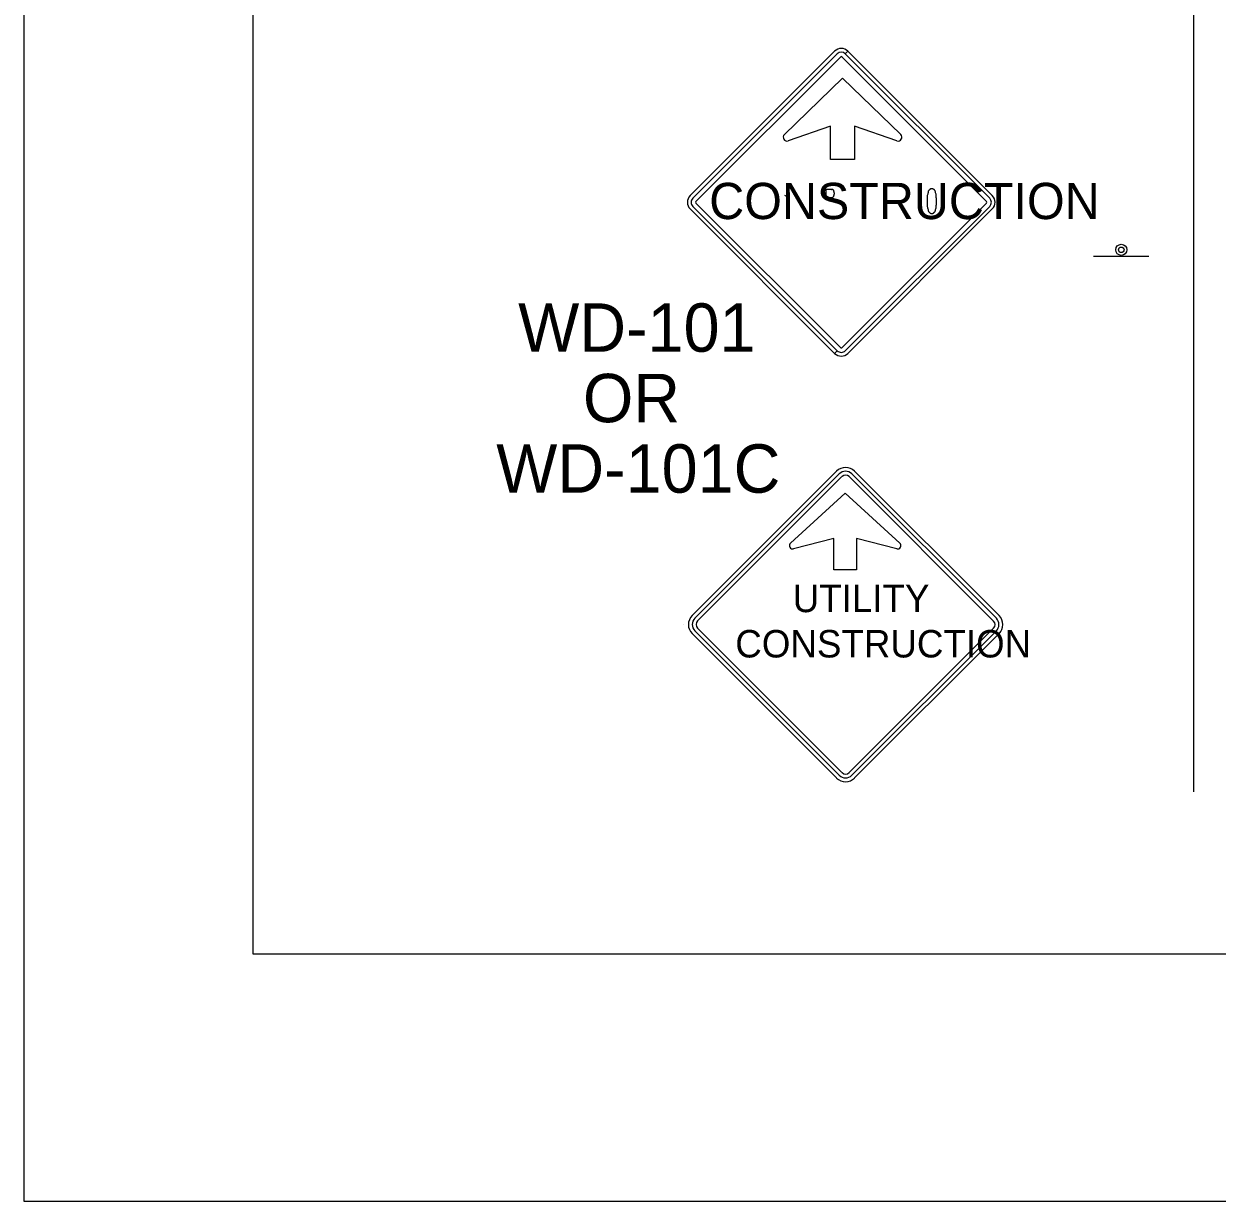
# Model space of a CAD drawing. Extents: x 1351 to 1567, y 178 to 457.
# Drawn here: x 1351.4 to 1403.6, y 177.9 to 229.4 of the extents above; entities that cross this region are included whole.
import ezdxf

# ---------------------------------------------------------------- set-up
doc = ezdxf.new("R2010")
doc.units = 0
for name, color, linetype in [('Level 1', 7, 'Continuous'), ('Level 10', 7, 'Continuous'), ('Level 44', 7, 'Continuous'), ('Level 60', 7, 'Continuous')]:
    doc.layers.add(name, color=color, linetype=linetype)

msp = doc.modelspace()

# ---------------------------------------------------------------- linework, layer by layer
at = {"layer": 'Level 1'}
for p, q in [((1380.523, 221.873), (1386.833, 228.183)), ((1380.523, 221.873), (1386.833, 228.183)), ((1380.638, 221.758), (1386.948, 228.068)), ((1380.638, 221.758), (1386.948, 228.068)), ((1380.776, 221.62), (1387.086, 227.93)), ((1380.776, 221.62), (1387.086, 227.93)), ((1387.164, 227.93), (1393.475, 221.62)), ((1387.164, 227.93), (1393.475, 221.62)), ((1387.417, 228.183), (1387.302, 228.068)), ((1387.417, 228.183), (1387.302, 228.068)), ((1387.302, 228.068), (1393.612, 221.758)), ((1387.302, 228.068), (1387.302, 228.068)), ((1387.302, 228.068), (1393.612, 221.758)), ((1387.302, 228.068), (1387.302, 228.068)), ((1387.417, 228.183), (1393.727, 221.873)), ((1387.417, 228.183), (1393.727, 221.873)), ((1384.64, 224.537), (1387.181, 227.012)), ((1384.64, 224.537), (1387.181, 227.012)), ((1387.182, 227.012), (1389.723, 224.537)), ((1387.182, 227.012), (1389.723, 224.537)), ((1386.655, 224.907), (1384.806, 224.268)), ((1386.655, 224.907), (1384.806, 224.268)), ((1386.655, 223.45), (1386.655, 224.907)), ((1386.655, 223.45), (1386.655, 224.907)), ((1389.557, 224.268), (1387.708, 224.907)), ((1387.708, 224.907), (1387.708, 223.45)), ((1389.557, 224.268), (1387.708, 224.907)), ((1387.708, 224.907), (1387.708, 223.45)), ((1387.708, 223.45), (1386.655, 223.45)), ((1387.708, 223.45), (1386.655, 223.45)), ((1386.684, 222.145), (1386.695, 222.145)), ((1386.684, 222.145), (1386.695, 222.145)), ((1386.684, 222.145), (1386.695, 222.145)), ((1386.684, 222.145), (1386.695, 222.145)), ((1386.833, 214.979), (1380.523, 221.289)), ((1386.833, 214.979), (1380.523, 221.289)), ((1386.948, 215.094), (1380.638, 221.404)), ((1386.948, 215.094), (1380.638, 221.404)), ((1387.086, 215.232), (1380.776, 221.542)), ((1387.086, 215.232), (1380.776, 221.542)), ((1393.475, 221.542), (1387.164, 215.232)), ((1393.475, 221.542), (1387.164, 215.232)), ((1393.612, 221.404), (1387.302, 215.094)), ((1393.612, 221.404), (1387.302, 215.094)), ((1393.727, 221.289), (1387.417, 214.979)), ((1393.727, 221.289), (1387.417, 214.979)), ((1386.948, 215.094), (1386.833, 214.979)), ((1386.948, 215.094), (1386.833, 214.979)), ((1386.833, 214.98), (1386.833, 214.979)), ((1386.833, 214.98), (1386.833, 214.979)), ((1386.948, 215.095), (1386.948, 215.094)), ((1386.948, 215.095), (1386.948, 215.094)), ((1387.101, 215.247), (1387.086, 215.232)), ((1387.101, 215.247), (1387.086, 215.232)), ((1385.04, 206.433), (1385.04, 206.433)), ((1385.04, 206.433), (1385.04, 206.433)), ((1385.04, 206.433), (1385.04, 206.433)), ((1385.04, 206.433), (1385.04, 206.433)), ((1385.04, 206.433), (1385.04, 206.433)), ((1385.04, 206.433), (1385.04, 206.433)), ((1380.216, 203.124), (1380.216, 203.124)), ((1380.216, 203.124), (1380.216, 203.124))]:
    msp.add_line(p, q, dxfattribs=at)
for points in [[(1386.695, 222.145), (1386.448, 222.145), (1386.448, 221.785), (1386.695, 221.785)], [(1386.695, 222.145), (1386.448, 222.145), (1386.448, 221.785), (1386.695, 221.785)], [(1386.695, 222.145), (1386.448, 222.145), (1386.448, 221.785), (1386.695, 221.785)], [(1386.695, 222.145), (1386.448, 222.145), (1386.448, 221.785), (1386.695, 221.785)], [(1386.684, 221.785), (1386.695, 221.785), (1386.707, 221.796), (1386.718, 221.796), (1386.729, 221.796), (1386.741, 221.796), (1386.741, 221.807), (1386.752, 221.807), (1386.763, 221.807), (1386.774, 221.819), (1386.786, 221.83), (1386.797, 221.841), (1386.808, 221.852), (1386.808, 221.864), (1386.808, 221.875), (1386.819, 221.897), (1386.819, 221.909), (1386.819, 221.92), (1386.819, 221.942), (1386.831, 221.954), (1386.831, 221.965), (1386.831, 221.987), (1386.819, 221.999), (1386.819, 222.01), (1386.819, 222.032), (1386.819, 222.044), (1386.808, 222.055), (1386.808, 222.078), (1386.797, 222.089), (1386.797, 222.1), (1386.786, 222.111), (1386.774, 222.111), (1386.774, 222.123), (1386.763, 222.123), (1386.752, 222.134), (1386.741, 222.134), (1386.729, 222.134), (1386.718, 222.145), (1386.707, 222.145), (1386.695, 222.145), (1386.684, 222.145)], [(1386.684, 221.785), (1386.695, 221.785), (1386.707, 221.796), (1386.718, 221.796), (1386.729, 221.796), (1386.741, 221.796), (1386.741, 221.807), (1386.752, 221.807), (1386.763, 221.807), (1386.774, 221.819), (1386.786, 221.83), (1386.797, 221.841), (1386.808, 221.852), (1386.808, 221.864), (1386.808, 221.875), (1386.819, 221.897), (1386.819, 221.909), (1386.819, 221.92), (1386.819, 221.942), (1386.831, 221.954), (1386.831, 221.965), (1386.831, 221.987), (1386.819, 221.999), (1386.819, 222.01), (1386.819, 222.032), (1386.819, 222.044), (1386.808, 222.055), (1386.808, 222.078), (1386.797, 222.089), (1386.797, 222.1), (1386.786, 222.111), (1386.774, 222.111), (1386.774, 222.123), (1386.763, 222.123), (1386.752, 222.134), (1386.741, 222.134), (1386.729, 222.134), (1386.718, 222.145), (1386.707, 222.145), (1386.695, 222.145), (1386.684, 222.145)], [(1386.684, 221.785), (1386.695, 221.785), (1386.707, 221.796), (1386.718, 221.796), (1386.729, 221.796), (1386.741, 221.796), (1386.741, 221.807), (1386.752, 221.807), (1386.763, 221.807), (1386.774, 221.819), (1386.786, 221.83), (1386.797, 221.841), (1386.808, 221.852), (1386.808, 221.864), (1386.808, 221.875), (1386.819, 221.897), (1386.819, 221.909), (1386.819, 221.92), (1386.819, 221.942), (1386.831, 221.954), (1386.831, 221.965), (1386.831, 221.987), (1386.819, 221.999), (1386.819, 222.01), (1386.819, 222.032), (1386.819, 222.044), (1386.808, 222.055), (1386.808, 222.078), (1386.797, 222.089), (1386.797, 222.1), (1386.786, 222.111), (1386.774, 222.111), (1386.774, 222.123), (1386.763, 222.123), (1386.752, 222.134), (1386.741, 222.134), (1386.729, 222.134), (1386.718, 222.145), (1386.707, 222.145), (1386.695, 222.145), (1386.684, 222.145)], [(1386.684, 221.785), (1386.695, 221.785), (1386.707, 221.796), (1386.718, 221.796), (1386.729, 221.796), (1386.741, 221.796), (1386.741, 221.807), (1386.752, 221.807), (1386.763, 221.807), (1386.774, 221.819), (1386.786, 221.83), (1386.797, 221.841), (1386.808, 221.852), (1386.808, 221.864), (1386.808, 221.875), (1386.819, 221.897), (1386.819, 221.909), (1386.819, 221.92), (1386.819, 221.942), (1386.831, 221.954), (1386.831, 221.965), (1386.831, 221.987), (1386.819, 221.999), (1386.819, 222.01), (1386.819, 222.032), (1386.819, 222.044), (1386.808, 222.055), (1386.808, 222.078), (1386.797, 222.089), (1386.797, 222.1), (1386.786, 222.111), (1386.774, 222.111), (1386.774, 222.123), (1386.763, 222.123), (1386.752, 222.134), (1386.741, 222.134), (1386.729, 222.134), (1386.718, 222.145), (1386.707, 222.145), (1386.695, 222.145), (1386.684, 222.145)], [(1390.93, 221.199), (1390.941, 221.188), (1390.941, 221.177), (1390.952, 221.165), (1390.964, 221.154), (1390.964, 221.143), (1390.975, 221.132), (1390.986, 221.132), (1390.997, 221.12), (1391.009, 221.12), (1391.009, 221.109), (1391.02, 221.109), (1391.031, 221.109), (1391.043, 221.098), (1391.054, 221.098), (1391.065, 221.098), (1391.076, 221.098), (1391.088, 221.098), (1391.099, 221.098), (1391.11, 221.098), (1391.121, 221.098), (1391.133, 221.109), (1391.144, 221.109), (1391.155, 221.109), (1391.166, 221.12), (1391.178, 221.132), (1391.189, 221.143), (1391.2, 221.143), (1391.2, 221.154), (1391.211, 221.165), (1391.223, 221.177), (1391.234, 221.188), (1391.234, 221.199), (1391.245, 221.233), (1391.245, 221.267), (1391.256, 221.301), (1391.268, 221.334), (1391.268, 221.368), (1391.279, 221.402), (1391.279, 221.447), (1391.29, 221.481), (1391.29, 221.515), (1391.29, 221.548), (1391.29, 221.582), (1391.29, 221.616), (1391.29, 221.65), (1391.29, 221.683), (1391.29, 221.717), (1391.29, 221.751), (1391.279, 221.796), (1391.279, 221.83), (1391.279, 221.864), (1391.268, 221.897), (1391.268, 221.931), (1391.256, 221.965), (1391.245, 221.999), (1391.245, 222.032), (1391.234, 222.066), (1391.223, 222.078), (1391.223, 222.089), (1391.211, 222.1), (1391.2, 222.111), (1391.2, 222.123), (1391.189, 222.134), (1391.178, 222.134), (1391.166, 222.145), (1391.155, 222.156), (1391.144, 222.156), (1391.133, 222.156), (1391.121, 222.168), (1391.11, 222.168), (1391.099, 222.168), (1391.088, 222.168), (1391.076, 222.168), (1391.065, 222.168), (1391.054, 222.168), (1391.043, 222.168), (1391.031, 222.168), (1391.02, 222.156), (1391.009, 222.156), (1391.009, 222.145), (1390.997, 222.145), (1390.986, 222.134), (1390.975, 222.134), (1390.975, 222.123), (1390.964, 222.111), (1390.952, 222.111), (1390.952, 222.1), (1390.941, 222.089), (1390.941, 222.078), (1390.93, 222.066), (1390.93, 222.055), (1390.93, 222.044), (1390.93, 222.032), (1390.919, 221.999), (1390.907, 221.976), (1390.907, 221.942), (1390.896, 221.909), (1390.885, 221.875), (1390.885, 221.841), (1390.885, 221.807)], [(1390.93, 221.199), (1390.941, 221.188), (1390.941, 221.177), (1390.952, 221.165), (1390.964, 221.154), (1390.964, 221.143), (1390.975, 221.132), (1390.986, 221.132), (1390.997, 221.12), (1391.009, 221.12), (1391.009, 221.109), (1391.02, 221.109), (1391.031, 221.109), (1391.043, 221.098), (1391.054, 221.098), (1391.065, 221.098), (1391.076, 221.098), (1391.088, 221.098), (1391.099, 221.098), (1391.11, 221.098), (1391.121, 221.098), (1391.133, 221.109), (1391.144, 221.109), (1391.155, 221.109), (1391.166, 221.12), (1391.178, 221.132), (1391.189, 221.143), (1391.2, 221.143), (1391.2, 221.154), (1391.211, 221.165), (1391.223, 221.177), (1391.234, 221.188), (1391.234, 221.199), (1391.245, 221.233), (1391.245, 221.267), (1391.256, 221.301), (1391.268, 221.334), (1391.268, 221.368), (1391.279, 221.402), (1391.279, 221.447), (1391.29, 221.481), (1391.29, 221.515), (1391.29, 221.548), (1391.29, 221.582), (1391.29, 221.616), (1391.29, 221.65), (1391.29, 221.683), (1391.29, 221.717), (1391.29, 221.751), (1391.279, 221.796), (1391.279, 221.83), (1391.279, 221.864), (1391.268, 221.897), (1391.268, 221.931), (1391.256, 221.965), (1391.245, 221.999), (1391.245, 222.032), (1391.234, 222.066), (1391.223, 222.078), (1391.223, 222.089), (1391.211, 222.1), (1391.2, 222.111), (1391.2, 222.123), (1391.189, 222.134), (1391.178, 222.134), (1391.166, 222.145), (1391.155, 222.156), (1391.144, 222.156), (1391.133, 222.156), (1391.121, 222.168), (1391.11, 222.168), (1391.099, 222.168), (1391.088, 222.168), (1391.076, 222.168), (1391.065, 222.168), (1391.054, 222.168), (1391.043, 222.168), (1391.031, 222.168), (1391.02, 222.156), (1391.009, 222.156), (1391.009, 222.145), (1390.997, 222.145), (1390.986, 222.134), (1390.975, 222.134), (1390.975, 222.123), (1390.964, 222.111), (1390.952, 222.111), (1390.952, 222.1), (1390.941, 222.089), (1390.941, 222.078), (1390.93, 222.066), (1390.93, 222.055), (1390.93, 222.044), (1390.93, 222.032), (1390.919, 221.999), (1390.907, 221.976), (1390.907, 221.942), (1390.896, 221.909), (1390.885, 221.875), (1390.885, 221.841), (1390.885, 221.807)], [(1390.93, 221.199), (1390.941, 221.188), (1390.941, 221.177), (1390.952, 221.165), (1390.964, 221.154), (1390.964, 221.143), (1390.975, 221.132), (1390.986, 221.132), (1390.997, 221.12), (1391.009, 221.12), (1391.009, 221.109), (1391.02, 221.109), (1391.031, 221.109), (1391.043, 221.098), (1391.054, 221.098), (1391.065, 221.098), (1391.076, 221.098), (1391.088, 221.098), (1391.099, 221.098), (1391.11, 221.098), (1391.121, 221.098), (1391.133, 221.109), (1391.144, 221.109), (1391.155, 221.109), (1391.166, 221.12), (1391.178, 221.132), (1391.189, 221.143), (1391.2, 221.143), (1391.2, 221.154), (1391.211, 221.165), (1391.223, 221.177), (1391.234, 221.188), (1391.234, 221.199), (1391.245, 221.233), (1391.245, 221.267), (1391.256, 221.301), (1391.268, 221.334), (1391.268, 221.368), (1391.279, 221.402), (1391.279, 221.447), (1391.29, 221.481), (1391.29, 221.515), (1391.29, 221.548), (1391.29, 221.582), (1391.29, 221.616), (1391.29, 221.65), (1391.29, 221.683), (1391.29, 221.717), (1391.29, 221.751), (1391.279, 221.796), (1391.279, 221.83), (1391.279, 221.864), (1391.268, 221.897), (1391.268, 221.931), (1391.256, 221.965), (1391.245, 221.999), (1391.245, 222.032), (1391.234, 222.066), (1391.223, 222.078), (1391.223, 222.089), (1391.211, 222.1), (1391.2, 222.111), (1391.2, 222.123), (1391.189, 222.134), (1391.178, 222.134), (1391.166, 222.145), (1391.155, 222.156), (1391.144, 222.156), (1391.133, 222.156), (1391.121, 222.168), (1391.11, 222.168), (1391.099, 222.168), (1391.088, 222.168), (1391.076, 222.168), (1391.065, 222.168), (1391.054, 222.168), (1391.043, 222.168), (1391.031, 222.168), (1391.02, 222.156), (1391.009, 222.156), (1391.009, 222.145), (1390.997, 222.145), (1390.986, 222.134), (1390.975, 222.134), (1390.975, 222.123), (1390.964, 222.111), (1390.952, 222.111), (1390.952, 222.1), (1390.941, 222.089), (1390.941, 222.078), (1390.93, 222.066), (1390.93, 222.055), (1390.93, 222.044), (1390.93, 222.032), (1390.919, 221.999), (1390.907, 221.976), (1390.907, 221.942), (1390.896, 221.909), (1390.885, 221.875), (1390.885, 221.841), (1390.885, 221.807)], [(1390.93, 221.199), (1390.941, 221.188), (1390.941, 221.177), (1390.952, 221.165), (1390.964, 221.154), (1390.964, 221.143), (1390.975, 221.132), (1390.986, 221.132), (1390.997, 221.12), (1391.009, 221.12), (1391.009, 221.109), (1391.02, 221.109), (1391.031, 221.109), (1391.043, 221.098), (1391.054, 221.098), (1391.065, 221.098), (1391.076, 221.098), (1391.088, 221.098), (1391.099, 221.098), (1391.11, 221.098), (1391.121, 221.098), (1391.133, 221.109), (1391.144, 221.109), (1391.155, 221.109), (1391.166, 221.12), (1391.178, 221.132), (1391.189, 221.143), (1391.2, 221.143), (1391.2, 221.154), (1391.211, 221.165), (1391.223, 221.177), (1391.234, 221.188), (1391.234, 221.199), (1391.245, 221.233), (1391.245, 221.267), (1391.256, 221.301), (1391.268, 221.334), (1391.268, 221.368), (1391.279, 221.402), (1391.279, 221.447), (1391.29, 221.481), (1391.29, 221.515), (1391.29, 221.548), (1391.29, 221.582), (1391.29, 221.616), (1391.29, 221.65), (1391.29, 221.683), (1391.29, 221.717), (1391.29, 221.751), (1391.279, 221.796), (1391.279, 221.83), (1391.279, 221.864), (1391.268, 221.897), (1391.268, 221.931), (1391.256, 221.965), (1391.245, 221.999), (1391.245, 222.032), (1391.234, 222.066), (1391.223, 222.078), (1391.223, 222.089), (1391.211, 222.1), (1391.2, 222.111), (1391.2, 222.123), (1391.189, 222.134), (1391.178, 222.134), (1391.166, 222.145), (1391.155, 222.156), (1391.144, 222.156), (1391.133, 222.156), (1391.121, 222.168), (1391.11, 222.168), (1391.099, 222.168), (1391.088, 222.168), (1391.076, 222.168), (1391.065, 222.168), (1391.054, 222.168), (1391.043, 222.168), (1391.031, 222.168), (1391.02, 222.156), (1391.009, 222.156), (1391.009, 222.145), (1390.997, 222.145), (1390.986, 222.134), (1390.975, 222.134), (1390.975, 222.123), (1390.964, 222.111), (1390.952, 222.111), (1390.952, 222.1), (1390.941, 222.089), (1390.941, 222.078), (1390.93, 222.066), (1390.93, 222.055), (1390.93, 222.044), (1390.93, 222.032), (1390.919, 221.999), (1390.907, 221.976), (1390.907, 221.942), (1390.896, 221.909), (1390.885, 221.875), (1390.885, 221.841), (1390.885, 221.807)], [(1384.815, 221.785), (1384.657, 221.875)], [(1384.815, 221.785), (1384.657, 221.875)], [(1390.885, 221.807), (1390.874, 221.774), (1390.874, 221.74), (1390.874, 221.706), (1390.874, 221.672), (1390.874, 221.638), (1390.874, 221.605), (1390.874, 221.571), (1390.874, 221.537), (1390.874, 221.503), (1390.885, 221.469), (1390.885, 221.436), (1390.885, 221.402), (1390.896, 221.368), (1390.896, 221.334), (1390.907, 221.301), (1390.919, 221.267), (1390.919, 221.233), (1390.93, 221.199)], [(1390.885, 221.807), (1390.874, 221.774), (1390.874, 221.74), (1390.874, 221.706), (1390.874, 221.672), (1390.874, 221.638), (1390.874, 221.605), (1390.874, 221.571), (1390.874, 221.537), (1390.874, 221.503), (1390.885, 221.469), (1390.885, 221.436), (1390.885, 221.402), (1390.896, 221.368), (1390.896, 221.334), (1390.907, 221.301), (1390.919, 221.267), (1390.919, 221.233), (1390.93, 221.199)], [(1390.885, 221.807), (1390.874, 221.774), (1390.874, 221.74), (1390.874, 221.706), (1390.874, 221.672), (1390.874, 221.638), (1390.874, 221.605), (1390.874, 221.571), (1390.874, 221.537), (1390.874, 221.503), (1390.885, 221.469), (1390.885, 221.436), (1390.885, 221.402), (1390.896, 221.368), (1390.896, 221.334), (1390.907, 221.301), (1390.919, 221.267), (1390.919, 221.233), (1390.93, 221.199)], [(1390.885, 221.807), (1390.874, 221.774), (1390.874, 221.74), (1390.874, 221.706), (1390.874, 221.672), (1390.874, 221.638), (1390.874, 221.605), (1390.874, 221.571), (1390.874, 221.537), (1390.874, 221.503), (1390.885, 221.469), (1390.885, 221.436), (1390.885, 221.402), (1390.896, 221.368), (1390.896, 221.334), (1390.907, 221.301), (1390.919, 221.267), (1390.919, 221.233), (1390.93, 221.199)], [(1380.61, 203.519), (1386.921, 209.829)], [(1380.61, 203.519), (1386.921, 209.829)], [(1380.728, 203.401), (1387.039, 209.711)], [(1380.728, 203.401), (1387.039, 209.711)], [(1387.59, 209.711), (1393.902, 203.398)], [(1387.59, 209.711), (1393.902, 203.398)], [(1387.709, 209.828), (1394.021, 203.516)], [(1387.709, 209.828), (1394.021, 203.516)], [(1380.847, 203.282), (1387.158, 209.592)], [(1380.847, 203.282), (1387.158, 209.592)], [(1387.473, 209.592), (1393.784, 203.279)], [(1387.473, 209.592), (1393.784, 203.279)], [(1384.906, 206.688), (1387.294, 208.862), (1389.685, 206.688)], [(1384.906, 206.688), (1387.294, 208.862), (1389.685, 206.688)], [(1384.906, 206.688), (1387.294, 208.862), (1389.685, 206.688)], [(1384.906, 206.688), (1387.294, 208.862), (1389.685, 206.688)], [(1384.906, 206.688), (1387.294, 208.862), (1389.685, 206.688)], [(1384.906, 206.688), (1387.294, 208.862), (1389.685, 206.688)], [(1389.547, 206.433), (1387.791, 206.885), (1387.791, 205.516), (1386.802, 205.516), (1386.802, 206.885), (1385.04, 206.433)], [(1389.547, 206.433), (1387.791, 206.885), (1387.791, 205.516), (1386.802, 205.516), (1386.802, 206.885), (1385.04, 206.433)], [(1389.547, 206.433), (1387.791, 206.885), (1387.791, 205.516), (1386.802, 205.516), (1386.802, 206.885), (1385.04, 206.433)], [(1389.547, 206.433), (1387.791, 206.885), (1387.791, 205.516), (1386.802, 205.516), (1386.802, 206.885), (1385.04, 206.433)], [(1389.547, 206.433), (1387.791, 206.885), (1387.791, 205.516), (1386.802, 205.516), (1386.802, 206.885), (1385.04, 206.433)], [(1389.547, 206.433), (1387.791, 206.885), (1387.791, 205.516), (1386.802, 205.516), (1386.802, 206.885), (1385.04, 206.433)], [(1387.039, 196.537), (1380.728, 202.848)], [(1387.039, 196.537), (1380.728, 202.848)], [(1387.158, 196.654), (1380.847, 202.966)], [(1387.158, 196.654), (1380.847, 202.966)], [(1393.784, 202.964), (1387.473, 196.654)], [(1393.784, 202.964), (1387.473, 196.654)], [(1393.902, 202.846), (1387.591, 196.537)], [(1393.902, 202.846), (1387.591, 196.537)], [(1386.921, 196.418), (1380.61, 202.729)], [(1386.921, 196.418), (1380.61, 202.729)], [(1394.021, 202.728), (1387.709, 196.418)], [(1394.021, 202.728), (1387.709, 196.418)]]:
    msp.add_lwpolyline(points, dxfattribs=at)
for centre, radius, start, end in [((1387.125, 227.892), 0.413, 45.0001, 135), ((1387.125, 227.892), 0.413, 45.0001, 135), ((1387.125, 227.892), 0.25, 45.0001, 135), ((1387.125, 227.892), 0.25, 45.0001, 135), ((1387.125, 227.892), 0.0552, 45, 135), ((1387.125, 227.892), 0.0552, 45, 135), ((1384.753, 224.422), 0.162, 134.244, 289.0634), ((1384.753, 224.422), 0.162, 134.244, 289.0634), ((1389.61, 224.422), 0.162, 250.9366, 45.756), ((1389.61, 224.422), 0.162, 250.9366, 45.756), ((1380.815, 221.581), 0.413, 135, 225), ((1380.815, 221.581), 0.413, 135, 225), ((1380.815, 221.581), 0.25, 135, 225.0007), ((1380.815, 221.581), 0.25, 135, 225.0007), ((1380.815, 221.581), 0.0552, 135, 225), ((1380.815, 221.581), 0.0552, 135, 225), ((1393.435, 221.581), 0.0552, 315, 44.9983), ((1393.435, 221.581), 0.0552, 315, 44.9983), ((1393.435, 221.581), 0.25, 315, 45), ((1393.435, 221.581), 0.25, 315, 45), ((1393.435, 221.581), 0.413, 315, 45), ((1393.435, 221.581), 0.413, 315, 45), ((1387.125, 215.271), 0.413, 225, 315), ((1387.125, 215.271), 0.413, 225, 315), ((1387.125, 215.271), 0.25, 224.9995, 315.0003), ((1387.125, 215.271), 0.25, 224.9995, 315.0003), ((1387.125, 215.271), 0.0553, 225, 315.0007), ((1387.125, 215.271), 0.0553, 225, 315.0007), ((1387.316, 209.433), 0.558, 44.995, 134.995), ((1387.316, 209.433), 0.558, 44.995, 134.995), ((1387.316, 209.433), 0.558, 44.995, 134.995), ((1387.316, 209.433), 0.558, 44.995, 134.995), ((1387.316, 209.433), 0.39, 44.995, 134.995), ((1387.316, 209.433), 0.39, 44.995, 134.995), ((1387.316, 209.433), 0.223, 44.995, 134.995), ((1387.316, 209.433), 0.223, 44.995, 134.995), ((1385.007, 206.577), 0.15, 132.3048, 284.4075), ((1385.007, 206.577), 0.15, 132.3048, 284.4075), ((1385.007, 206.577), 0.15, 132.3048, 284.4075), ((1385.007, 206.577), 0.15, 132.3048, 284.4075), ((1385.007, 206.577), 0.15, 132.3048, 284.4075), ((1385.007, 206.577), 0.15, 132.3048, 284.4075), ((1389.586, 206.577), 0.15, 255.5925, 47.6952), ((1389.586, 206.577), 0.15, 255.5925, 47.6952), ((1389.586, 206.577), 0.15, 255.5925, 47.6952), ((1389.586, 206.577), 0.15, 255.5925, 47.6952), ((1389.586, 206.577), 0.15, 255.5925, 47.6952), ((1389.586, 206.577), 0.15, 255.5925, 47.6952), ((1381.005, 203.124), 0.558, 134.9949, 224.9949), ((1381.005, 203.124), 0.558, 134.9949, 224.9949), ((1381.005, 203.124), 0.39, 134.9949, 224.9949), ((1381.005, 203.124), 0.39, 134.9949, 224.9949), ((1393.627, 203.121), 0.39, 314.995, 44.995), ((1393.627, 203.121), 0.39, 314.995, 44.995), ((1393.627, 203.121), 0.558, 314.995, 44.995), ((1393.627, 203.121), 0.558, 314.995, 44.995), ((1381.005, 203.124), 0.223, 134.9949, 224.9949), ((1381.005, 203.124), 0.223, 134.9949, 224.9949), ((1393.627, 203.121), 0.223, 314.995, 44.995), ((1393.627, 203.121), 0.223, 314.995, 44.995), ((1387.316, 196.812), 0.223, 224.995, 314.9949), ((1387.316, 196.812), 0.223, 224.995, 314.9949), ((1387.316, 196.812), 0.558, 224.995, 314.9949), ((1387.316, 196.812), 0.558, 224.995, 314.9949), ((1387.316, 196.812), 0.39, 224.995, 314.9949), ((1387.316, 196.812), 0.39, 224.995, 314.9949)]:
    msp.add_arc(centre, radius, start, end, dxfattribs=at)
at = {"layer": 'Level 10'}
msp.add_line((1402.517, 372.998), (1402.517, 195.81), dxfattribs=at)
at = {"layer": 'Level 44'}
msp.add_line((1398.146, 219.233), (1400.565, 219.233), dxfattribs=at)
for radius in [0.242, 0.121]:
    msp.add_circle((1399.36, 219.504), radius, dxfattribs=at)
at = {"layer": 'Level 60'}
for p, q in [((1361.408, 188.732), (1361.408, 188.732)), ((1351.408, 177.923), (1351.408, 177.923))]:
    msp.add_line(p, q, dxfattribs=at)
for points in [[(1567.408, 456.923), (1351.408, 456.923), (1351.408, 177.923), (1567.408, 177.923)], [(1548.282, 446.114), (1361.408, 446.114), (1361.408, 188.732), (1548.282, 188.732)]]:
    msp.add_lwpolyline(points, close=True, dxfattribs=at)

# ---------------------------------------------------------------- texts
at = {"layer": 'Level 1'}
for s, height, p in [('CONSTRUCTION', 1.584, (1381.355, 220.847)), ('CONSTRUCTION', 1.584, (1381.355, 220.847)), ('UTILITY', 1.2, (1385.005, 203.667)), ('UTILITY', 1.2, (1385.005, 203.667)), ('CONSTRUCTION', 1.2, (1382.496, 201.686)), ('CONSTRUCTION', 1.2, (1382.496, 201.686))]:
    msp.add_text(s, height=height, dxfattribs=at).set_placement(p)
at = {"layer": 'Level 10'}
for s, p in [('WD-101', (1373.008, 215.048)), ('OR', (1375.839, 211.968)), ('WD-101C', (1372.049, 208.888))]:
    msp.add_text(s, height=2.1151, rotation=360, dxfattribs=at).set_placement(p)

doc.saveas('drawing.dxf')
